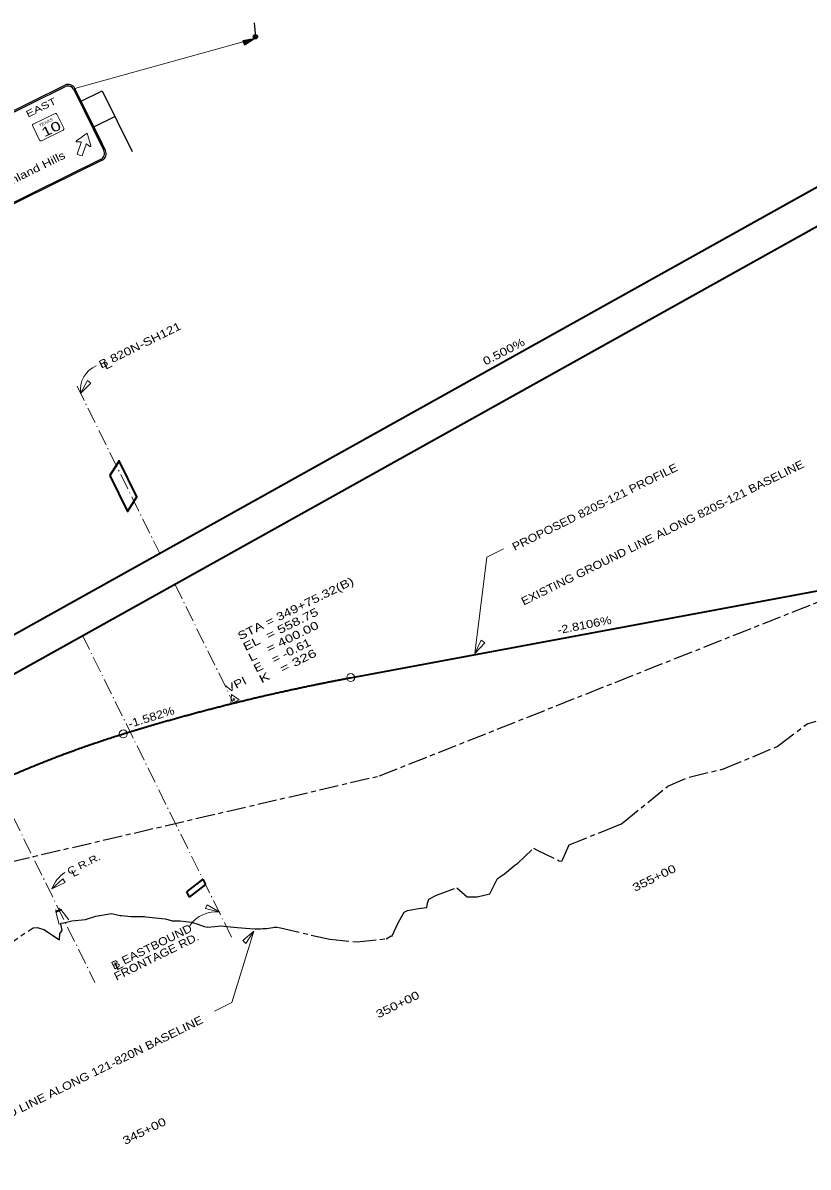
# Model space of a CAD drawing. Extents: x 2356431 to 2371438, y 6972864 to 6982525.
# Drawn here: x 2362955 to 2364327, y 6975574 to 6977575 of the extents above; entities that cross this region are included whole.
import ezdxf
from ezdxf.enums import TextEntityAlignment as Align

# ---------------------------------------------------------------- set-up
doc = ezdxf.new("R2010")
doc.units = 0
doc.header["$LTSCALE"] = 5.6
for name, pattern in [('DOT_DASHED', [7.7, 5, -1.2, 0.3, -1.2]), ('LONG_DASH_SHORT_DASH', [9.9, 6, -1.2, 1.5, -1.2]), ('LONG_DASHED', [7.5, 6, -1.5])]:
    doc.linetypes.add(name, pattern=pattern)
for name, color, linetype, lineweight in [('1', 7, 'Continuous', 25), ('2', 7, 'Continuous', 35), ('4', 7, 'LONG_DASHED', 35), ('40', 7, 'Continuous', 35), ('44', 7, 'Continuous', 13), ('48', 7, 'Continuous', 25), ('52', 7, 'Continuous', 25), ('53', 7, 'Continuous', 13), ('61', 7, 'Continuous', 13)]:
    doc.layers.add(name, color=color, linetype=linetype, lineweight=lineweight)

msp = doc.modelspace()

# ---------------------------------------------------------------- hatches: boundary and pattern name
at = {"layer": '48'}
for points in [[(2363358.816, 6977547.15), (2363339.583, 6977543.741), (2363342.122, 6977537.006)], [(2363364.959, 6977549.51, 1), (2363358.031, 6977552.287, 1)]]:
    msp.add_hatch(color=256, dxfattribs=at).paths.add_polyline_path(points)

# ---------------------------------------------------------------- linework, layer by layer
at = {"layer": '1', "lineweight": 13}
for p, q in [((2363123.235, 6976809.109), (2363106.828, 6976783.677)), ((2363154.205, 6976746.432), (2363137.777, 6976720.969)), ((2363012.872, 6976023.789), (2363012.225, 6976023.47)), ((2363012.541, 6976020.394), (2363018.785, 6975998.168)), ((2363014.155, 6976021.191), (2363012.871, 6976023.794)), ((2363012.872, 6976023.789), (2363013.284, 6976023.993)), ((2363018.612, 6976026.622), (2363017.917, 6976026.279)), ((2363018.612, 6976026.622), (2363019.108, 6976026.867)), ((2363019.894, 6976024.023), (2363018.676, 6976026.491)), ((2363021.622, 6976024.876), (2363035.465, 6976006.4))]:
    msp.add_line(p, q, dxfattribs=at)
at = {"layer": '1', "linetype": 'LONG_DASH_SHORT_DASH'}
msp.add_line((2363578.139, 6976258.258), (2364790.419, 6976739.461), dxfattribs=at)
at = {"layer": '1', "linetype": 'DOT_DASHED', "lineweight": 13}
msp.add_line((2363319.609, 6975976.555), (2363060.36, 6976501.85), dxfattribs=at)
at = {"layer": '1', "lineweight": 35}
for p, q in [((2363269.399, 6976077.538), (2363241.228, 6976055.546)), ((2363274.188, 6976068.59), (2363245.56, 6976046.241))]:
    msp.add_line(p, q, dxfattribs=at)
at = {"layer": '1', "linetype": 'LONG_DASH_SHORT_DASH'}
for points in [[(2363853.011, 6976129.175), (2363892.086, 6976110.059), (2363897, 6976109.346), (2363898.567, 6976112.631), (2363909.772, 6976137.514), (2363993.269, 6976171.427), (2364000.327, 6976174.141), (2364002.636, 6976175.382), (2364004.36, 6976177.04), (2364082.157, 6976240.452), (2364119.731, 6976256.353), (2364179.542, 6976270.437), (2364269.391, 6976308.223), (2364273.243, 6976309.819), (2364275.929, 6976311.56), (2364325.581, 6976349.133), (2364341.661, 6976353.884)], [(2362551.137, 6975979.346), (2362642.186, 6976020.825), (2362736.378, 6976055.937), (2362833.536, 6976085.04), (2362933.658, 6976108.135), (2363578.139, 6976258.258)], [(2362918.187, 6975956.071), (2362973.22, 6975992.777), (2362979.915, 6975993.315), (2362991.666, 6975989.739), (2363018.949, 6975971.393), (2363019.884, 6975982.434), (2363023.934, 6975987.782), (2363021.522, 6975999.771), (2363021.565, 6976000.835), (2363026.189, 6976001.116), (2363028.238, 6976001.867), (2363029.064, 6976002.115), (2363040.764, 6976004.622), (2363064.753, 6976007.363), (2363082.774, 6976013.106), (2363109.768, 6976017.914), (2363124.892, 6976014.193), (2363125.433, 6976014.114), (2363127.22, 6976013.953), (2363143.61, 6976012.456), (2363165.913, 6976012.559), (2363167.376, 6976012.554), (2363170.107, 6976011.905), (2363204.088, 6976008.376), (2363215.72, 6976004.839), (2363230.247, 6976004.785), (2363249.521, 6976002.532), (2363261.123, 6975999.076), (2363271.926, 6975994.981), (2363278.147, 6975993.656), (2363290.529, 6975994.897), (2363301.083, 6975995.933), (2363329.623, 6975993.257), (2363351.801, 6975991.649), (2363360.436, 6975990.993), (2363370.584, 6975990.728), (2363374.513, 6975991.195), (2363381.502, 6975991.408), (2363392.215, 6975993.431), (2363394.507, 6975993.736), (2363396.823, 6975993.971), (2363399.005, 6975993.935), (2363405.486, 6975992.829), (2363458.68, 6975980.015), (2363491.453, 6975972.792), (2363539.149, 6975967.876), (2363590.179, 6975973.636), (2363598.487, 6975978.854), (2363600.113, 6975977.393), (2363610.939, 6976001.124), (2363621.702, 6976019.927), (2363626.989, 6976022.974), (2363646.522, 6976026.673), (2363661.206, 6976027.906), (2363662.512, 6976035.555), (2363664.712, 6976042.838), (2363677.868, 6976049.465), (2363713.211, 6976062.703), (2363731.75, 6976047.064), (2363748.299, 6976046.961), (2363748.668, 6976046.778), (2363749.305, 6976046.843), (2363771.066, 6976052.287), (2363784.5, 6976078.685), (2363784.654, 6976078.802), (2363784.649, 6976078.903), (2363784.654, 6976079.005), (2363784.675, 6976079.03), (2363796.941, 6976087.321), (2363815, 6976102.105), (2363816.778, 6976103.201), (2363820.032, 6976105.918), (2363847.357, 6976131.947), (2363853.011, 6976129.175)]]:
    msp.add_lwpolyline(points, dxfattribs=at)
at = {"layer": '1', "lineweight": 13}
for centre, radius, start, end in [((2363101.18, 6976933.393), 45.636, 113.21271, 187.66561), ((2363057.457, 6976043.179), 54.396, 122.29505, 161.25905), ((2363292.729, 6975963.808), 56.695, 83.45242, 144.3988)]:
    msp.add_arc(centre, radius, start, end, dxfattribs=at)
at = {"layer": '2', "lineweight": 13}
for q in [(2363745.086, 6976472.136), (2363795.25, 6976655.366)]:
    msp.add_line((2363765.949, 6976640.905), q, dxfattribs=at)
at = {"layer": '2'}
msp.add_line((2363527.851, 6976429.977), (2364482.273, 6976608.067), dxfattribs=at)
msp.add_lwpolyline([(2363106.828, 6976783.677), (2363137.777, 6976720.969), (2363154.205, 6976746.432), (2363123.235, 6976809.109)], close=True, dxfattribs=at)
at = {"layer": '2', "lineweight": 13}
for points in [[(2363762.219, 6976491.141), (2363745.086, 6976472.136), (2363756.118, 6976495.465)], [(2363339.332, 6975970.254), (2363359.01, 6975986.61), (2363344.752, 6975965.101)]]:
    msp.add_lwpolyline(points, close=True, dxfattribs=at)
msp.add_lwpolyline([(2363289.958, 6975846.905), (2363320.42, 6975861.939), (2363359.01, 6975986.61)], dxfattribs=at)
at = {"layer": '2'}
for points in [[(2363130.277, 6976331.73), (2363138.015, 6976334.126), (2363145.763, 6976336.505), (2363153.518, 6976338.867), (2363161.283, 6976341.211), (2363169.056, 6976343.537), (2363176.838, 6976345.846), (2363184.628, 6976348.137), (2363192.427, 6976350.411), (2363200.235, 6976352.666), (2363208.052, 6976354.905), (2363215.877, 6976357.125), (2363223.711, 6976359.328), (2363231.554, 6976361.513), (2363239.405, 6976363.681), (2363247.266, 6976365.831), (2363255.134, 6976367.963), (2363263.012, 6976370.078), (2363270.898, 6976372.175), (2363278.793, 6976374.255), (2363286.697, 6976376.316), (2363294.609, 6976378.361), (2363302.53, 6976380.387), (2363310.46, 6976382.396), (2363318.398, 6976384.388), (2363326.345, 6976386.362), (2363334.301, 6976388.318), (2363342.266, 6976390.256), (2363350.239, 6976392.177), (2363358.221, 6976394.08), (2363366.212, 6976395.966), (2363374.211, 6976397.834), (2363382.219, 6976399.685), (2363390.236, 6976401.517), (2363398.261, 6976403.332), (2363406.295, 6976405.13), (2363414.338, 6976406.91), (2363422.39, 6976408.672), (2363430.45, 6976410.416), (2363438.519, 6976412.144), (2363446.596, 6976413.853), (2363454.683, 6976415.545), (2363462.778, 6976417.219), (2363470.881, 6976418.876), (2363478.994, 6976420.514), (2363487.115, 6976422.136), (2363495.245, 6976423.739), (2363503.384, 6976425.325), (2363511.531, 6976426.894), (2363519.687, 6976428.444), (2363527.851, 6976429.977)], [(2362243.124, 6975755.334), (2362258.347, 6975771.967), (2362273.674, 6975788.391), (2362289.102, 6975804.608), (2362304.634, 6975820.616), (2362320.27, 6975836.415), (2362336.007, 6975852.006), (2362351.848, 6975867.389), (2362367.791, 6975882.563), (2362383.837, 6975897.529), (2362399.986, 6975912.287), (2362416.238, 6975926.836), (2362432.593, 6975941.177), (2362449.049, 6975955.31), (2362465.61, 6975969.234), (2362482.274, 6975982.95), (2362499.039, 6975996.457), (2362515.908, 6976009.756), (2362532.879, 6976022.846), (2362549.954, 6976035.729), (2362567.132, 6976048.403), (2362584.412, 6976060.868), (2362601.795, 6976073.125), (2362619.28, 6976085.174), (2362636.869, 6976097.015), (2362654.561, 6976108.647), (2362672.355, 6976120.071), (2362690.253, 6976131.286), (2362708.252, 6976142.293), (2362726.355, 6976153.092), (2362744.562, 6976163.682), (2362762.87, 6976174.063), (2362781.281, 6976184.237), (2362799.795, 6976194.202), (2362818.412, 6976203.959), (2362837.133, 6976213.507), (2362855.955, 6976222.847), (2362874.881, 6976231.979), (2362893.909, 6976240.901), (2362913.041, 6976249.616), (2362932.275, 6976258.123), (2362951.612, 6976266.421), (2362971.052, 6976274.511), (2362990.594, 6976282.392), (2363010.239, 6976290.065), (2363029.988, 6976297.53), (2363049.839, 6976304.786), (2363069.793, 6976311.834), (2363089.849, 6976318.673), (2363110.01, 6976325.304), (2363130.272, 6976331.727)]]:
    msp.add_spline(points, degree=3, dxfattribs=at)
at = {"layer": '4'}
msp.add_line((2363012.541, 6976020.394), (2363021.509, 6976024.82), dxfattribs=at)
at = {"layer": '40'}
msp.add_line((2363130.272, 6976331.727), (2363130.277, 6976331.73), dxfattribs=at)
at = {"layer": '44', "linetype": 'DOT_DASHED'}
for p, q in [((2363049.817, 6976939.863), (2363194.175, 6976647.363)), ((2363221.017, 6976592.975), (2363323.353, 6976385.621)), ((2362842.346, 6976380.537), (2363080.839, 6975897.303))]:
    msp.add_line(p, q, dxfattribs=at)
at = {"layer": '44', "linetype": 'DOT_DASHED', "lineweight": 35}
msp.add_line((2363269.668, 6976077.747), (2363274.188, 6976068.59), dxfattribs=at)
at = {"layer": '44', "lineweight": 35}
msp.add_line((2363241.04, 6976055.399), (2363245.56, 6976046.241), dxfattribs=at)
at = {"layer": '44'}
msp.add_line((2363021.509, 6976024.82), (2363012.541, 6976020.394), dxfattribs=at)
at = {"layer": '48'}
for p, q in [((2363359.349, 6977575.152), (2363361.495, 6977550.903)), ((2362843.723, 6977375.028), (2363028.65, 6977466.288)), ((2362846.238, 6977373.582), (2363028.257, 6977463.422)), ((2363093.498, 6977364.069), (2363045.944, 6977460.424)), ((2363099.399, 6977352.111), (2363045.944, 6977460.424)), ((2363096.516, 6977352.496), (2363044.49, 6977457.912)), ((2363057.002, 6977438.335), (2363093.86, 6977456.527)), ((2363093.86, 6977456.526), (2363146.301, 6977350.271)), ((2363079.132, 6977393.498), (2363115.99, 6977411.688)), ((2363093.53, 6977334.816), (2362908.612, 6977243.538)), ((2363091.003, 6977336.271), (2362908.984, 6977246.431))]:
    msp.add_line(p, q, dxfattribs=at)
at = {"layer": '48', "lineweight": 13}
for p, q in [((2363045.949, 6977460.423), (2363358.816, 6977547.151)), ((2363011.37, 6977416.826), (2362973.348, 6977398.053)), ((2363026.793, 6977391.065), (2363014.618, 6977415.735)), ((2362972.241, 6977394.821), (2362984.414, 6977370.157)), ((2362987.667, 6977369.053), (2363025.684, 6977387.823))]:
    msp.add_line(p, q, dxfattribs=at)
at = {"layer": '48'}
msp.add_lwpolyline([(2363358.816, 6977547.15), (2363339.583, 6977543.741), (2363342.122, 6977537.006)], close=True, dxfattribs=at)
msp.add_circle((2363361.495, 6977550.899), 3.732, dxfattribs=at)
for centre, radius, start, end in [((2363033.631, 6977452.544), 12.111, 26.26515, 116.26515), ((2363034.365, 6977454.707), 12.919, 26.26515, 116.26515), ((2363085.644, 6977347.129), 12.111, 296.26515, 26.26515), ((2363087.807, 6977346.395), 12.919, 296.26515, 26.26515)]:
    msp.add_arc(centre, radius, start, end, dxfattribs=at)
at = {"layer": '48', "lineweight": 13}
for centre, start, end in [((2363012.445, 6977414.655), 26.26515, 116.26515), ((2362974.418, 6977395.89), 116.26515, 206.26515), ((2363024.614, 6977389.994), 296.26515, 26.26515), ((2362986.587, 6977371.228), 206.26515, 296.26515)]:
    msp.add_arc(centre, 2.422, start, end, dxfattribs=at)
at = {"layer": '53', "lineweight": 35}
for p, q in [((2362763.128, 6976407.438), (2364813.246, 6977550.503)), ((2362792.347, 6976355.033), (2364749.113, 6977446.049))]:
    msp.add_line(p, q, dxfattribs=at)
at = {"layer": '53'}
for p, q in [((2363056.091, 6977366.973), (2363049.496, 6977366.853)), ((2363065.492, 6977362.934), (2363065.422, 6977362.922)), ((2363071.934, 6977359.084), (2363066.79, 6977363.29))]:
    msp.add_line(p, q, dxfattribs=at)
for points in [[(2363048.778, 6977369.089), (2363067.419, 6977382.544), (2363073.816, 6977360.428)], [(2363065.422, 6977362.922), (2363058.532, 6977342.598), (2363054.116, 6977344.111), (2363049.842, 6977345.592), (2363056.948, 6977365.891)]]:
    msp.add_lwpolyline(points, dxfattribs=at)
for points in [[(2363074.079, 6976945.366), (2363055.952, 6976927.305), (2363068.217, 6976950.009)], [(2363028.824, 6976072.116), (2363005.945, 6976060.655), (2363024.715, 6976078.364)], [(2363277.149, 6976033.124), (2363299.194, 6976020.132), (2363274.132, 6976026.282)]]:
    msp.add_lwpolyline(points, close=True, dxfattribs=at)
for centre, radius, start, end in [((2363049.492, 6977368.086), 1.215, 125.62527, 271.00641), ((2363056.155, 6977366.17), 0.81, 340.88678, 90.86988), ((2363066.258, 6977362.669), 0.81, 50.90367, 160.88678), ((2363072.678, 6977360.051), 1.215, 230.76714, 16.14828)]:
    msp.add_arc(centre, radius, start, end, dxfattribs=at)
at = {"layer": '61'}
for p, q in [((2363319.755, 6976400.367), (2363318.774, 6976384.24)), ((2363319.755, 6976400.367), (2363333.234, 6976391.459)), ((2363318.774, 6976384.24), (2363333.234, 6976391.459))]:
    msp.add_line(p, q, dxfattribs=at)
for centre, radius in [((2363528.075, 6976430.252), 7), ((2363323.913, 6976392.014), 1.5), ((2363130.574, 6976331.856), 7)]:
    msp.add_circle(centre, radius, dxfattribs=at)

# ---------------------------------------------------------------- texts
at = {"layer": '1'}
for s, height, width, p in [('B 820N-SH121', 14, 1.25, (2363162.58, 6977005.121)), ('L', 14, 1.4, (2363106.079, 6976971.629)), ('C R.R.', 12, 1.3, (2363064.276, 6976098.88)), ('L', 12, 1.4, (2363048.814, 6976083.836)), ('B EASTBOUND', 14, 1.15, (2363183.136, 6975953.126)), ('FRONTAGE RD.', 14, 1.15, (2363191.593, 6975936.111)), ('L', 14, 1.4, (2363125.189, 6975921.094))]:
    msp.add_text(s, height=height, rotation=26.268, dxfattribs=dict(at, width=width)).set_placement(p, align=Align.CENTER)
at = {"layer": '2'}
for s, rotation, width, p in [('0.500%', 27.409, 1.25, (2363763.614, 6976975.84)), ('-2.8106%', 11.137, 1.2, (2363890.5, 6976506.024)), ('-1.582%', 17.255, 1.2, (2363141.428, 6976342.001))]:
    msp.add_text(s, height=14, rotation=rotation, dxfattribs=dict(at, width=width)).set_placement(p)
for s, width, p in [('PROPOSED 820S-121 PROFILE', 1.15, (2363957.875, 6976722.294)), ('EXISTING GROUND LINE ALONG 121-820N BASELINE', 1.2, (2363014.623, 6975700.159))]:
    msp.add_text(s, height=14, rotation=26.268, dxfattribs=dict(at, width=width)).set_placement(p, align=Align.CENTER)
at = {"layer": '44', "width": 1.15}
msp.add_text('EXISTING GROUND LINE ALONG 820S-121 BASELINE', height=14, rotation=26.268, dxfattribs=at).set_placement((2364075.966, 6976677.343), align=Align.CENTER)
at = {"layer": '48'}
for s, height, rotation, width, p in [('EAST', 11.63, 26.264, 1.4, (2362989.406, 6977422.05)), ('Richland Hills', 13.5, 26.27, 1.25, (2362969.503, 6977308.844))]:
    msp.add_text(s, height=height, rotation=rotation, dxfattribs=dict(at, width=width)).set_placement(p, align=Align.CENTER)
for s, height, width, p in [('TEXAS', 5.167, 1.15, (2362984.814, 6977393.061)), ('10', 16.15, 1.45, (2362992.506, 6977374.866))]:
    msp.add_text(s, height=height, rotation=26.265, dxfattribs=dict(at, width=width)).set_placement(p)
at = {"layer": '52'}
for s, width, p in [('STA = 349+75.32(B)', 1.3, (2363334.769, 6976495.435)), ('EL  = 558.75', 1.35, (2363344.062, 6976476.604)), ('L   = 400.00', 1.35, (2363353.356, 6976457.773)), ('E   = -0.61', 1.25, (2363362.65, 6976438.941)), ('K   = 326', 1.45, (2363371.944, 6976420.11))]:
    msp.add_text(s, height=14, rotation=26.268, dxfattribs=dict(at, width=width)).set_placement(p)
at = {"layer": '53', "width": 1.3}
for s, p in [('355+00', (2364061.451, 6976073.541)), ('350+00', (2363613.013, 6975852.222)), ('345+00', (2363170.373, 6975630.924))]:
    msp.add_text(s, height=14, rotation=26.268, dxfattribs=at).set_placement(p, align=Align.CENTER)
at = {"layer": '61', "width": 1.25}
msp.add_text('VPI', height=14, rotation=26.531, dxfattribs=at).set_placement((2363330.613, 6976411.893), align=Align.CENTER)

doc.saveas('drawing.dxf')
